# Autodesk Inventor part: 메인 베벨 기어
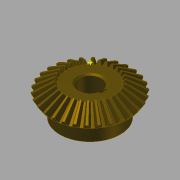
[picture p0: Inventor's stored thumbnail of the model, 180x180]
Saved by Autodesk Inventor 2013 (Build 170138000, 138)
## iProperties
Created: 2014-10
Part Number: 메인 베벨 기어
Material: 강철, 탄소
Document SubType Name: Modeling
Designer: KYOUNG IL JANG
Categories: <?xml version="1.0" encoding="UTF-16"?> <MemberInstance><Categories><FamilyTemplate><FamilyTemplateParameter ValueType="xs:double" Id="1" ObjectReferenceKey="da
Mass: 269.926 g
Surface Area: 108.837 cm^2
Volume: 34.2981 cm^3
Density: 7.87 g/cm^3
CustomPartVersion: 1
da_b: 14.400 mm
da_de: 60.000 mm
da_dae: 62.219 mm
da_dfe: 57.337 mm
da_le: 36.056 mm
da_omega: 90.00 deg
da_beta: 0.00 deg
da_delta: 56.31 deg
da_alpha: 20.00 deg
da_he: 4.400 mm
da_ve: 18.336 mm
da_z: 30.000 ul
da_z2: 20.000 ul
fd_dv: 108.167 mm
fd_dva: 112.167 mm
fd_dvb: 101.643 mm
da_zv: 54.083 ul
fd_loft: 14.620 mm
fd_ratio: 0.596 ul
fd_rr: 19.188 mm
fd_angle: 1.68 deg
fd_x1: 1.588 mm
fd_y1: 54.060 mm
fd_x2: 17.869 mm
fd_y2: 6.991 mm
fd_x: 19.457 mm
fd_y: 47.069 mm
fd_angle2: 19.68 deg
fd_dd: 108.647 mm
da_dvw: 108.167 mm
da_dm: 48.018 mm
da_x: 0.000 ul
da_m: 2.000 mm
da_teethtype: 0.000 ul
d56: 10.373 mm
d0: 60.000 mm
d1: 57.337 mm
d2: 62.219 mm
d3: 14.400 mm
d4: 18.336 mm
d7: 19.188 mm
d8: 19.457 mm
d9: 47.069 mm
d11: 14.620 mm
d12: 11.427 mm
d15: 11.587 mm
d16: 28.030 mm
d17: 0.000 ul
d18: 90.00 deg
d19: 0.000 ul
d20: 90.00 deg
d21: 30.000 ul
d22: 360.00 deg
d26: 229.906 mm
d27: 8.110 mm
d28: 60.000 mm
d29: -56.31 deg
d30: 11.427 mm
d31: 11.587 mm
d32: 28.030 mm
d35: 0.000 ul
d37: 0.000 ul
d39: 0.000 ul
d40: 90.00 deg
d41: 30.000 ul
d42: 360.00 deg
d48: 0.000 mm
d49: 0.000 mm
d50: 90.00 deg
d51: 6.00 deg
d52: 0.000 mm
d53: 0.000 mm
d54: 0.00 deg
d57: 57.403 mm
d58: 51.155 mm
d59: 34.184 mm
d60: 30.464 mm
d61: 34.184 mm
d62: 30.464 mm
d65: 229.906 mm
d66: 3.150 ul
d67: 60.000 mm
d68: -56.31 deg
d69: 8.110 mm
d70: 11.587 mm
d71: 28.030 mm
d72: 11.427 mm
d73: 30.464 mm
d74: 34.184 mm
d75: 0.000 ul
d77: 0.000 ul
d79: 0.000 ul
d80: 90.00 deg
d81: 30.000 ul
d82: 360.00 deg
d84: 1.000 ul
d85: 2.000 ul
d86: 2.000 ul
d87: 1.000 ul
d88: 0.000 ul
d89: 0.000 ul
d90: 90.00 deg
d91: 90.00 deg
d92: 90.00 deg
d93: 90.00 deg
d94: 45.000 mm
d95: 13.000 mm
d96: 0.00 deg
d97: 17.000 mm
d104: 5.000 mm
d107: 0.00 deg
d108: 1.000 mm
d111: 2.000 mm
d112: 19.300 mm
Author: SeoGD™ [www.esajin.kr]
Revision Number: 1
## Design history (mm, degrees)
node "맨 위 점"
node "메쉬 평면2"
sketch "톱니 본체 스케치"
  geometry: L1 (0, 0)-(28.669, -21.997); L2 (28.669, -21.997)-(31.109, -18.336); L3 (31.109, -18.336)-(0, 0); L4 (30, -20)-(0, 0); L5 (17.219, -13.212)-(18.685, -11.013); L6 (28.669, -21.997)-(17.219, -13.212); L7 (31.109, -18.336)-(18.685, -11.013); L8 (0, -39.387)-(0, 6.564) reference; L9 (0, -20)-(31.109, -20)
  constraints: 16 end point, 4 point on line, 3 perpendicular, 2 collinear, 1 horizontal alignment, 1 vertical alignment
  dimensions: "d0" = 60 diameter of L4.start L8 (= da_de); "d1" = 57.33744 diameter of L1.end L8 (= da_dfe); "d2" = 62.2188 diameter of L2.end L8 (= da_dae); "d3" = 14.4 distance between parallel lines of L2 L5 (= da_b); "d4" = 18.3359 vertical distance of L2.end L1.start (= da_ve)
revolve "톱니 본체" sketch "톱니 본체 스케치" stored, may be unused: angle "d5" = 90 deg
node "시작점"
node "톱니 평면"
sketch "시작 스케치"
  geometry: L1 (0, -23.505)-(0, 10.645) reference; L2 (-0.709, -2.928)-(0.709, -2.928); A1 r 19.188 centre (-19.457, -7.014) between (-0.709, -2.928) and (-3.232, 3.229); A2 r 19.188 centre (19.457, -7.014) between (3.232, 3.229) and (0.709, -2.928); A3 r 57.403 centre (0, -54.083) between (3.232, 3.229) and (-3.232, 3.229); 1 further point
  constraints: 6 point on circle, 3 centre point, 3 symmetric about line, 2 end point, 1 coincident, 1 perpendicular, 1 other
  dimensions: "d7" = 19.18795 radius of A1 (= fd_rr); "d8" = 19.45712 horizontal distance of point (0, -54.083) A1.centre (= fd_x); "d9" = 47.06905 vertical distance of point (0, -54.083) A1.centre (= fd_y); "d57" = 57.40327 radius of A3 (= 0.5 x fd_dva + 0.3 x da_he); "d58" = 51.15527 distance from line of A3.centre L2 (= 0.5 x fd_dva - 1.12 x da_he)
node "끝점"
  node "끝 평면"
sketch "3D 스케치 오른쪽"
  node "Helical Curve Right" dims "d65" = 229.90621 (computed from da_dm, da_delta, da_beta), count "d66" = 3.15, "d67" = 60 (= da_de), angle "d68" = -56.3099 deg (= -da_delta), "d69" = 8.10972 (computed from fd_loft, da_delta)
node "끝 평면 오른쪽"
sketch "끝 스케치 오른쪽"
  geometry: L1 (0, -41.54)-(0, 13.178) reference; L2 (-0.422, -1.69)-(0.422, -1.69); A1 r 11.427 centre (-11.587, -4.123) between (-0.422, -1.69) and (-1.925, 1.977); A2 r 11.427 centre (11.587, -4.123) between (1.925, 1.977) and (0.422, -1.69); A3 r 34.184 centre (0, -32.153) between (1.925, 1.977) and (-1.925, 1.977); 1 further point
  constraints: 6 point on circle, 3 centre point, 3 symmetric about line, 2 end point, 1 coincident, 1 perpendicular, 1 other
  dimensions: "d70" = 11.58699 horizontal distance of A3.centre A1.centre (computed from fd_x, fd_ratio); "d71" = 28.03028 vertical distance of point (0, -32.153) A1.centre (computed from fd_y, fd_ratio); "d72" = 11.4267 radius of A1 (computed from fd_rr, fd_ratio); "d73" = 30.46369 distance from line of point (0, -32.153) L2 (computed from d58, fd_ratio); "d74" = 34.18446 radius of A3 (computed from d57, fd_ratio)
feature "로프트 오른쪽" sketch "끝 스케치 오른쪽" dims count "d75" = 0, count "d77" = 0, count "d79" = 0, angle "d80" = 90 deg, count "d85" = 2, angle "d92" = 90 deg, angle "d93" = 90 deg, count "da_teethtype" = 0 [user parameter]
sketch "3D 스케치 왼쪽"
  node "Helical Curve Left" dims "d26" = 229.90621 (computed from da_dm, da_delta, da_beta), "d27" = 8.10972 (computed from fd_loft, da_delta), "d28" = 60 (= da_de), angle "d29" = -56.3099 deg (= -da_delta)
node "끝 평면 왼쪽"
sketch "끝 스케치 왼쪽" dims "d56" = 10.3728 (derived)
  geometry: L1 (0, -43.753)-(0, 15.405) reference; L2 (-0.422, -1.678)-(0.422, -1.678); A1 r 11.427 centre (-11.587, -4.111) between (-0.422, -1.678) and (-1.925, 1.988); A2 r 11.427 centre (11.587, -4.111) between (1.925, 1.988) and (0.422, -1.678); A3 r 34.184 centre (0, -32.142) between (1.925, 1.988) and (-1.925, 1.988); 2 further points; 1 other entity
  constraints: 6 point on circle, 3 centre point, 3 symmetric about line, 2 end point, 1 coincident, 2 other
  dimensions: "d30" = 11.4267 radius of A1 (computed from fd_rr, fd_ratio); "d31" = 11.58699 horizontal distance of point (0, -32.142) A1.centre (computed from fd_x, fd_ratio); "d32" = 28.03028 vertical distance of A1.centre point (0, -32.142) (computed from fd_y, fd_ratio); "d61" = 34.18446 radius of A3 (computed from d57, fd_ratio); "d62" = 30.46369 distance from line of point (0, -32.142) L2 (computed from d58, fd_ratio)
feature "로프트 왼쪽" sketch "끝 스케치 왼쪽" dims count "d35" = 0, count "d37" = 0, count "d39" = 0, angle "d40" = 90 deg, count "d84" = 1, angle "d90" = 90 deg, angle "d91" = 90 deg, count "da_teethtype" = 0 [user parameter]
sketch "본체 스케치"
  geometry: L1 (0, -35.038)-(0, -19.531) reference; L2 (28.669, -21.997)-(17.219, -13.212) reference; L3 (17.219, -13.212)-(0, -13.212); L4 (28.669, -21.997)-(0, -21.997)
  constraints: 4 end point, 2 perpendicular, 2 point on line
revolve "본체 고정" sketch "본체 스케치" stored, may be unused: angle "d46" = 90 deg
feature "피치 지름" dims angle "d47" = 90 deg
sketch "스케치8"
  geometry: C1 r 22.5 at (0, 0); 1 further point
  constraints: 1 centre point, 1 coincident
  dimensions: "d94" = 45 diameter of C1
extrude "돌출1" join sketch "스케치8" distance "d95" = 13; taper "d96" = 0 deg
sketch "스케치9"
  geometry: 1 further point
hole "구멍1" sketch "스케치9" at (0, 0) diameter "d97" = 17; stored, may be unused: countersink angle "d101" = 90 deg, drill point angle "d103" = 118 deg; dims "d98" = 6, "d99" = 4, "d100" = 2, "d102" = 8
sketch "스케치10"
  geometry: L1 (8.124, 2.5)-(10.8, 2.5); L2 (10.8, 2.5)-(10.8, -2.5); L3 (10.8, -2.5)-(8.124, -2.5); A1 r 8.5 centre (0, 0) between (8.124, 2.5) and (8.124, -2.5) reference; 1 further point
  constraints: 6 end point, 2 parallel, 2 point on circle, 1 horizontal, 1 perpendicular
  dimensions: "d104" = 5 distance of L1.end L2.end; "d112" = 19.3 dimension on A1 L2
extrude "돌출2" cut sketch "스케치10" stored distance "d106" = 10; taper "d107" = 0 deg
chamfer "모따기1" distance "d108" = 1; stored, may be unused: second distance "d109" = 2, angle "d110" = 45 deg
fillet "모깎기1" dims "d111" = 2
body "Solid1"
feature "로프트" dims count "d17" = 0, angle "d18" = 90 deg, count "d19" = 0, angle "d20" = 90 deg, count "d89" = 0, count "da_teethtype" = 0 [user parameter]
pattern_circular "원형 패턴" dims count "d21" = 30 (= da_z), angle "d22" = 360 deg, count "d88" = 0, count "da_teethtype" = 0 [user parameter]
pattern_circular "원형 패턴 오른쪽" dims count "d81" = 30 (= da_z), angle "d82" = 360 deg, count "d86" = 2, count "da_teethtype" = 0 [user parameter]
pattern_circular "원형 패턴 왼쪽" dims count "d41" = 30 (= da_z), angle "d42" = 360 deg, count "d87" = 1, count "da_teethtype" = 0 [user parameter]
sketch "끝 스케치"
  geometry: L1 (0, -15.359)-(0, 6.983) reference; L2 (-0.422, -1.69)-(0.422, -1.69); A1 r 11.427 centre (-11.587, -4.123) between (-0.422, -1.69) and (-1.925, 1.977); A2 r 11.427 centre (11.587, -4.123) between (1.925, 1.977) and (0.422, -1.69); A3 r 34.184 centre (0, -32.153) between (1.925, 1.977) and (-1.925, 1.977); 1 further point
  constraints: 6 point on circle, 3 centre point, 3 symmetric about line, 2 end point, 1 coincident, 1 other
  dimensions: "d12" = 11.4267 radius of A1 (computed from fd_rr, fd_ratio); "d15" = 11.58699 horizontal distance of A1.centre point (0, -32.153) (computed from fd_x, fd_ratio); "d16" = 28.03028 vertical distance of A1.centre point (0, -32.153) (computed from fd_y, fd_ratio); "d59" = 34.18446 radius of A3 (computed from d57, fd_ratio); "d60" = 30.46369 distance from line of A3.centre L2 (computed from d58, fd_ratio)
sketch "Sketch6"
  geometry: L1 (30, -20)-(0, 0) reference; L2 (0, -37.8)-(0, 6.3) reference
body "Srf1"
other parameters: "da_b" = 14.4 [user parameter; used in 2 equation terms], "da_de" = 60 [user parameter; used in 4 equation terms], "da_dae" = 62.2188 [user parameter; used in 2 equation terms], "da_dfe" = 57.33744 [user parameter; used in 1 equation term], "da_le" = 36.05551 [user parameter; used in 1 equation term], "da_omega" = 90 deg [user parameter; used in 1 equation term], "da_beta" = 0 deg [user parameter; used in 2 equation terms], "da_delta" = 56.3099 deg [user parameter; used in 8 equation terms], "da_alpha" = 20 deg [user parameter; used in 2 equation terms], "da_he" = 4.4 [user parameter; used in 4 equation terms], "da_ve" = 18.3359 [user parameter; used in 1 equation term], "da_z" = 30 [user parameter; used in 4 equation terms], "da_z2" = 20 [user parameter], "fd_dv" = 108.16654 (computed from da_de, da_delta) [user parameter; used in 1 equation term], "fd_dva" = 112.16654 (computed from da_dae, da_delta) [user parameter; used in 3 equation terms], "fd_dvb" = 101.6433 (computed from fd_dv, da_alpha) [user parameter; used in 2 equation terms], "da_zv" = 54.0833 [user parameter; used in 1 equation term], "fd_loft" = 14.62 (= da_b + 0.05 x da_he) [user parameter; used in 4 equation terms], "fd_ratio" = 0.595514 (computed from da_le, fd_loft) [user parameter; used in 15 equation terms], "fd_rr" = 19.18795 (computed from fd_dd, fd_dvb) [user parameter; used in 6 equation terms], "fd_angle" = 1.68259 deg (computed from da_zv) [user parameter; used in 4 equation terms], "fd_x1" = 1.58802 (computed from da_dvw, fd_angle) [user parameter; used in 1 equation term], "fd_y1" = 54.05995 (computed from da_dvw, fd_angle) [user parameter; used in 1 equation term], "fd_x2" = 17.8691 (computed from fd_rr, fd_angle2, fd_angle) [user parameter; used in 1 equation term], "fd_y2" = 6.9909 (computed from fd_rr, fd_angle2, fd_angle) [user parameter; used in 1 equation term], "fd_x" = 19.45712 (= fd_x1 + fd_x2) [user parameter; used in 4 equation terms], "fd_y" = 47.06905 (= fd_y1 - fd_y2) [user parameter; used in 4 equation terms], "fd_angle2" = 19.6843 deg (computed from fd_dvb, fd_dd, da_alpha) [user parameter; used in 2 equation terms], "fd_dd" = 108.64654 (= fd_dva - 0.8 x da_he) [user parameter; used in 2 equation terms], "da_dvw" = 108.16654 [user parameter; used in 2 equation terms], "d11" = 14.62 (= fd_loft), "da_dm" = 48.01848 [user parameter; used in 2 equation terms], "da_x" = 0 [user parameter], "da_m" = 2 [user parameter], "d48" = 0, "d49" = 0, "d50" = 90 deg (= da_omega), "d51" = 6 deg (computed from da_z), "d52" = 0, "d53" = 0, "d54" = 0 deg
